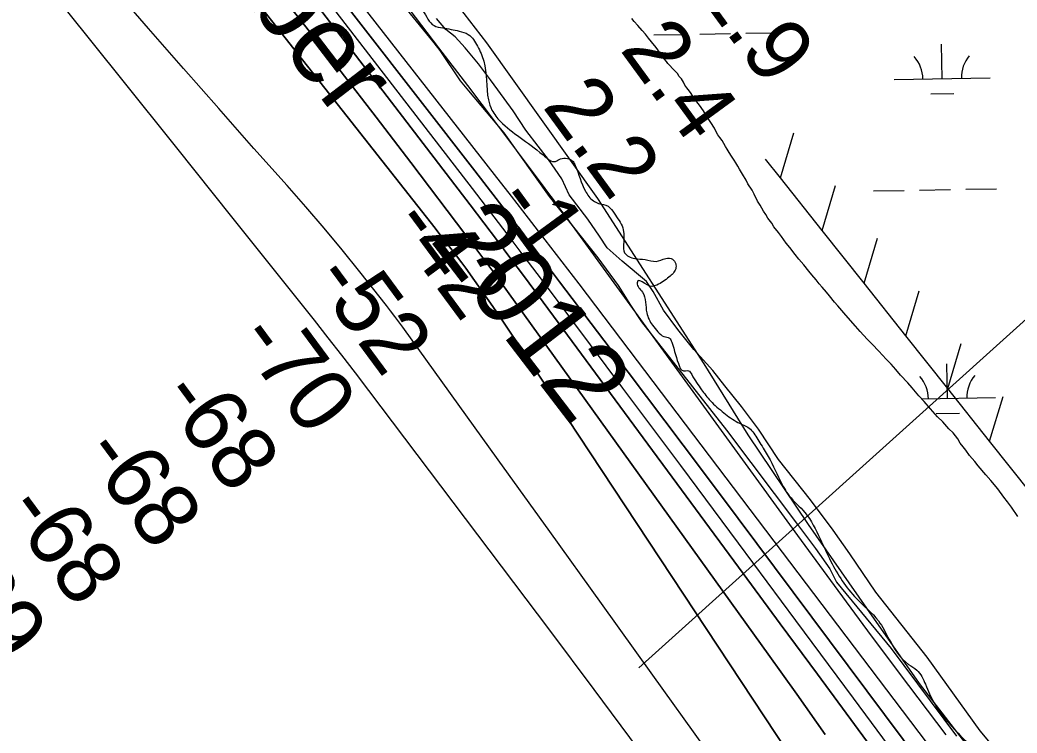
# Model space of a CAD drawing. Extents: x 3887375 to 3925618, y 296674 to 322633.
# Drawn here: x 3903484 to 3904521, y 303211 to 303953 of the extents above; entities that cross this region are included whole.
import ezdxf

# ---------------------------------------------------------------- set-up
doc = ezdxf.new("R2010")
doc.units = 0
for name, color, linetype in [('V-RIVR-EDGE', 7, 'Continuous'), ('V-RIVR-IDEN', 7, 'Continuous'), ('V-RIVR-JETY', 7, 'Continuous'), ('V-RIVR-RANG', 7, 'Continuous'), ('V-RRAP-FSHR', 7, 'Continuous'), ('V-TOPO-DPTH', 7, 'Continuous'), ('V-TOPO-MAJR', 7, 'Continuous'), ('V-TOPO-MINR', 7, 'Continuous'), ('V-TOPO-WATR', 7, 'Continuous'), ('V-WETL-SWMP', 7, 'Continuous')]:
    doc.layers.add(name, color=color, linetype=linetype)

msp = doc.modelspace()

# ---------------------------------------------------------------- linework, layer by layer
at = {"layer": 'V-RIVR-EDGE'}
msp.add_spline([(3903770.8, 304167), (3903771.4, 304174.6), (3903768.5, 304179.6), (3903762.5, 304179.3), (3903755.1, 304174.6), (3903752.1, 304164.7), (3903751.5, 304159), (3903754.8, 304151.4), (3903758.4, 304144.7), (3903757, 304137.4), (3903757, 304131.1), (3903762.3, 304125.4), (3903773.6, 304116.4), (3903785.6, 304106.1), (3903792.2, 304094.1), (3903793.5, 304088.8), (3903799.5, 304081.8), (3903811.4, 304070.8), (3903831.3, 304054.7), (3903842.3, 304049.1), (3903853.6, 304046.7), (3903858.3, 304053), (3903863.9, 304057.3), (3903875.9, 304060.3), (3903902.2, 304051.2), (3903921.7, 304037.9), (3903928.4, 304024.6), (3903933.7, 304014.9), (3903938.6, 304011.6), (3903950.6, 304007.9), (3903951.3, 304004.6), (3903936.6, 303996.3), (3903920, 303988), (3903913.3, 303987.4), (3903903.7, 303986.1), (3903899, 303985.4), (3903896, 303988.4), (3903894.7, 303993.7), (3903890.4, 303996.4), (3903886.4, 303993.4), (3903885, 303990.4), (3903885.4, 303984.8), (3903888, 303978.4), (3903902.9, 303962.1), (3903914.5, 303946.8), (3903923.5, 303944.4), (3903940.8, 303941.1), (3903950.1, 303937.7), (3903959.7, 303925.4), (3903966.3, 303909.8), (3903971.2, 303869.5), (3903974.8, 303858.9), (3903983.5, 303847.2), (3904004, 303830.5), (3904027.9, 303812.2), (3904040.9, 303805.5), (3904046.2, 303808.1), (3904059.2, 303805.4), (3904061.5, 303801.4), (3904072.1, 303774.5), (3904080.3, 303764.5), (3904085.7, 303761.8), (3904095.6, 303758.8), (3904101.9, 303751.5), (3904110.9, 303736.5), (3904111.8, 303719.2), (3904112.8, 303710.5), (3904123.4, 303704.5), (3904134.1, 303703.5), (3904145.7, 303701.5), (3904155.7, 303704.4), (3904162.7, 303703.8), (3904166, 303699.1), (3904166, 303693.8), (3904159, 303685.1), (3904146.3, 303676.9), (3904141, 303675.5), (3904131, 303680.2), (3904126.7, 303681.2), (3904126, 303679.2), (3904131.3, 303669.6), (3904135.9, 303648), (3904141.9, 303635), (3904147.5, 303628.3), (3904153.8, 303623.3), (3904159.5, 303621.6), (3904161.8, 303617.6), (3904170, 303592), (3904172.4, 303588.3), (3904176.3, 303587.7), (3904179.3, 303587.7), (3904182.7, 303583.7), (3904192.9, 303568), (3904202.2, 303556.3), (3904216.1, 303544), (3904230.8, 303534), (3904242.4, 303528), (3904251.3, 303516.3), (3904260.3, 303502), (3904274.8, 303473.4), (3904284.1, 303457.7), (3904300.4, 303440.4), (3904316.2, 303412.7), (3904327.5, 303389.4), (3904354, 303350.8), (3904376.9, 303327.5), (3904388.1, 303308.2), (3904408.4, 303282.2), (3904417, 303276.2), (3904425.9, 303261.5), (3904434.9, 303242.2), (3904460.1, 303210.5), (3904493.5, 303168.2), (3904499.5, 303156.2), (3904515.4, 303136.2), (3904535.3, 303109.9), (3904550.9, 303088.9), (3904578.1, 303056), (3904601.9, 303022), (3904623.1, 302991.7), (3904644, 302960.4), (3904673.8, 302922.4), (3904699.4, 302886.1), (3904723.2, 302853.7), (3904742.4, 302827.4), (3904786.2, 302772.8), (3904807.1, 302745.5), (3904837.2, 302707.5), (3904854.8, 302680.5), (3904867.1, 302662.5), (3904915.8, 302598.2), (3904946.6, 302556.9), (3904978.4, 302512.3), (3905022.2, 302457.3), (3905048.4, 302422.6), (3905069.2, 302392.3), (3905083.5, 302372.7), (3905098, 302354.4)], degree=3, dxfattribs=at)
at = {"layer": 'V-RIVR-JETY'}
for points in [[(3903886.6, 303963), (3903912.8, 303930.6), (3903920.7, 303921), (3903941.7, 303889.5), (3903950.4, 303879), (3903987.1, 303835.3), (3904034.3, 303768.9), (3904085, 303705.1), (3904106, 303676.3), (3904119.1, 303656.1), (3904130.5, 303638.7), (3904218.8, 303525.9), (3904293.9, 303426.3), (3904311.4, 303402.7), (3904326.3, 303381.7), (3904333.3, 303367.7), (3904390.1, 303298.6), (3904458.3, 303207.7)], [(3904520.3, 303168.4), (3904482.7, 303213), (3904427.7, 303289.9), (3904374.4, 303357.2), (3904347.3, 303397.4), (3904329.8, 303421.9), (3904306.2, 303453.4), (3904273, 303495.3), (3904252, 303526.8), (3904234.5, 303550.4), (3904217, 303572.2), (3904204.8, 303588), (3904184.7, 303609.8), (3904168.1, 303630.8), (3904153.2, 303650.9), (3904142.7, 303670.1), (3904135.7, 303680.6), (3904110.4, 303701.6), (3904094.6, 303715.6), (3904086.8, 303727.8), (3904074.5, 303745.3), (3904055.3, 303770.7), (3904047.4, 303787.3), (3904033.5, 303807.4), (3904023, 303821.4), (3904009.9, 303838), (3903996.7, 303858.1), (3903981, 303879.9), (3903973.1, 303890.4), (3903960.9, 303907), (3903946.9, 303923.6), (3903936.4, 303935), (3903926.8, 303942.9), (3903917.2, 303954.2)]]:
    msp.add_lwpolyline(points, dxfattribs=at)
at = {"layer": 'V-RIVR-RANG'}
msp.add_line((3904647.8, 303747), (3904127.6, 303278.7), dxfattribs=at)
at = {"layer": 'V-RRAP-FSHR'}
for p, q in [((3904275, 303788.3), (3904288.8, 303835.1)), ((3904318.5, 303733.5), (3904332.4, 303780.3)), ((3904362.1, 303678.7), (3904376, 303725.5)), ((3904405.6, 303623.9), (3904419.5, 303670.7)), ((3904449.2, 303569.1), (3904463.1, 303615.9)), ((3904492.7, 303514.3), (3904506.6, 303561.1))]:
    msp.add_line(p, q, dxfattribs=at)
for points in [[(3903843.6, 304195.5), (3903802.2, 304154.3), (3903801.2, 304143.7), (3903845.4, 304089.4), (3903969.1, 303928.8), (3904084.5, 303767), (3904195.4, 303595), (3904241.1, 303521.1), (3904304, 303427.8), (3904364.7, 303340.8), (3904419.5, 303262.5), (3904542.9, 303102.6), (3904668, 302949.1), (3904792.2, 302791.8), (3904915.3, 302634.1), (3905037.8, 302475.9), (3905151.7, 302337.7)], [(3904275, 303788.3), (3904259.4, 303807.9)], [(3904318.5, 303733.5), (3904275, 303788.3)], [(3904362.1, 303678.7), (3904318.5, 303733.5)], [(3904405.6, 303623.9), (3904362.1, 303678.7)], [(3904449.2, 303569.1), (3904405.6, 303623.9)], [(3904492.7, 303514.3), (3904449.2, 303569.1)], [(3904536.3, 303459.5), (3904492.7, 303514.3)]]:
    msp.add_lwpolyline(points, dxfattribs=at)
at = {"layer": 'V-TOPO-DPTH'}
for points in [[(3904459.8, 303127.5), (3904230.9, 303434), (3904192.9, 303484.9), (3904154.7, 303535.7), (3904116.5, 303586.4), (3904078.1, 303637), (3904045.2, 303680.4), (3904023.2, 303709.3), (3904001.2, 303738.1), (3903979, 303766.9), (3903956.8, 303795.6), (3903662.9, 304174.5), (3903632.8, 304213.1), (3903602.6, 304251.6), (3903572.2, 304289.9), (3903541.7, 304328.2), (3903527.5, 304345.9), (3903504, 304375.1)], [(3903504, 304375.1), (3903527.5, 304345.9), (3903541.7, 304328.2), (3903572.2, 304289.9), (3903602.6, 304251.6), (3903632.8, 304213.1), (3903662.9, 304174.5), (3903956.8, 303795.6), (3903979, 303766.9), (3904001.2, 303738.1), (3904023.2, 303709.3), (3904045.2, 303680.4), (3904078.1, 303637), (3904116.5, 303586.4), (3904154.7, 303535.7), (3904192.9, 303484.9), (3904230.9, 303434), (3904459.8, 303127.5)], [(3904447.5, 303208.8), (3904408.5, 303260.4), (3904369.7, 303312.1), (3904331.3, 303364.2), (3904293.1, 303416.4), (3904050.2, 303750.3), (3904044.5, 303758), (3904038.8, 303765.8), (3904033.1, 303773.5), (3904027.4, 303781.1), (3903979.4, 303844.9), (3903949.6, 303884.4), (3903919.6, 303923.8), (3903889.5, 303963), (3903859.2, 304002.2), (3903567.5, 304378.2)], [(3904321.7, 303209.4), (3904292, 303251.2), (3904262.2, 303292.8), (3903976.6, 303689.9), (3903969.4, 303699.7), (3903962.3, 303709.5), (3903955, 303719.2), (3903947.7, 303728.9), (3903890.3, 303804.4), (3903854.2, 303851.7), (3903817.8, 303898.8), (3903781.2, 303945.7), (3903744.3, 303992.5), (3903456.7, 304355.3), (3903448.7, 304365.4)], [(3903448.7, 304365.4), (3903456.7, 304355.3), (3903744.3, 303992.5), (3903781.2, 303945.7), (3903817.8, 303898.8), (3903854.2, 303851.7), (3903890.3, 303804.4), (3903947.7, 303728.9), (3903955, 303719.2), (3903962.3, 303709.5), (3903969.4, 303699.7), (3903976.6, 303689.9), (3904262.2, 303292.8), (3904292, 303251.2), (3904321.7, 303209.4)], [(3903475.7, 304370.1), (3903491.3, 304350.7), (3903585.4, 304232.5), (3903647.8, 304153.8), (3903709.9, 304074.8), (3903771.6, 303995.4), (3903832.9, 303915.9), (3903952.1, 303760.2), (3903966.3, 303741.6), (3903980.5, 303722.9), (3903994.5, 303704.1), (3904008.5, 303685.3), (3904236.2, 303376.9), (3904274.8, 303324.5), (3904313.4, 303272.1), (3904352, 303219.7), (3904390.5, 303167.2)], [(3903475.7, 304370.1), (3903491.3, 304350.7), (3903585.4, 304232.5), (3903647.8, 304153.8), (3903709.9, 304074.8), (3903771.6, 303995.4), (3903832.9, 303915.9), (3903952.1, 303760.2), (3903966.3, 303741.6), (3903980.5, 303722.9), (3903994.5, 303704.1), (3904008.5, 303685.3), (3904236.2, 303376.9), (3904274.8, 303324.5), (3904313.4, 303272.1), (3904352, 303219.7), (3904390.5, 303167.2)], [(3904367, 303063.3), (3904004.8, 303611.4), (3903995.2, 303625.8), (3903985.4, 303640.2), (3903975.6, 303654.6), (3903965.6, 303668.8), (3903947.5, 303694.5), (3903944.5, 303698.5), (3903943.5, 303699.9), (3903935.7, 303710.2), (3903930.7, 303716.7), (3903925.7, 303723.1), (3903920.7, 303729.6), (3903915.7, 303736), (3903423.8, 304359.8), (3903422.1, 304362)], [(3903422.1, 304362), (3903423.8, 304359.8), (3903915.7, 303736), (3903920.7, 303729.6), (3903925.7, 303723.1), (3903930.7, 303716.7), (3903935.7, 303710.2), (3903943.5, 303699.9), (3903944.5, 303698.5), (3903947.5, 303694.5), (3903965.6, 303668.8), (3903975.6, 303654.6), (3903985.4, 303640.2), (3903995.2, 303625.8), (3904004.8, 303611.4), (3904367, 303063.3)]]:
    msp.add_lwpolyline(points, dxfattribs=at)
at = {"layer": 'V-TOPO-MAJR'}
msp.add_lwpolyline([(3904195.9, 303196.1), (3904142.3, 303270.9), (3904088.7, 303345.7), (3904035.1, 303420.4), (3903981.3, 303495.1), (3903882.1, 303632.9), (3903877.9, 303638.6), (3903873.6, 303644.3), (3903869.3, 303650), (3903864.9, 303655.6), (3903837.3, 303690.5), (3903818.9, 303713.4), (3903800.2, 303736), (3903781.1, 303758.3), (3903761.7, 303780.4), (3903727.1, 303819.1), (3903690.4, 303860.5), (3903653.8, 303902.1), (3903617.5, 303943.9), (3903581.3, 303985.8), (3903451.4, 304137.7)], dxfattribs=at)
at = {"layer": 'V-TOPO-MINR'}
for points in [[(3904127.3, 303194.1), (3904081.2, 303256), (3904035, 303317.7), (3903846.7, 303567.3), (3903832.7, 303585.6), (3903818.6, 303603.9), (3903804.4, 303622.1), (3903790.1, 303640.2), (3903704.2, 303747.7), (3903646.9, 303819.5), (3903589.5, 303891.2), (3903532.2, 303963), (3903474.8, 304034.7), (3903327.7, 304218.3), (3903308.7, 304242.1), (3903289.8, 304265.9), (3903270.9, 304289.7), (3903252.1, 304313.6), (3903172.5, 304414.6), (3903114.1, 304489.1), (3903056.1, 304563.9), (3902998.5, 304639.1), (3902941.2, 304714.5)], [(3904459.8, 303127.5), (3904230.9, 303434), (3904192.9, 303484.9), (3904154.7, 303535.7), (3904116.5, 303586.4), (3904078.1, 303637), (3904045.2, 303680.4), (3904023.2, 303709.3), (3904001.2, 303738.1), (3903979, 303766.9), (3903956.8, 303795.6), (3903662.9, 304174.5), (3903632.8, 304213.1), (3903602.6, 304251.6), (3903572.2, 304289.9), (3903541.7, 304328.2), (3903527.5, 304345.9), (3903504, 304375.1)], [(3904494.2, 303112.6), (3904117.7, 303609.6), (3904100.3, 303632.5), (3904082.9, 303655.4), (3904065.4, 303678.2), (3904047.9, 303701), (3904030.3, 303723.8), (3904012.7, 303746.6), (3903995, 303769.3), (3903977.3, 303791.9), (3903577.4, 304303.8), (3903563.1, 304321.9), (3903548.8, 304340), (3903534.5, 304358.1), (3903520, 304376.1)], [(3904321.7, 303209.4), (3904292, 303251.2), (3904262.2, 303292.8), (3903976.6, 303689.9), (3903969.4, 303699.7), (3903962.3, 303709.5), (3903955, 303719.2), (3903947.7, 303728.9), (3903890.3, 303804.4), (3903854.2, 303851.7), (3903817.8, 303898.8), (3903781.2, 303945.7), (3903744.3, 303992.5), (3903456.7, 304355.3), (3903448.7, 304365.4)], [(3904390.5, 303167.2), (3904352, 303219.7), (3904313.4, 303272.1), (3904274.8, 303324.5), (3904236.2, 303376.9), (3904008.5, 303685.3), (3903994.5, 303704.1), (3903980.5, 303722.9), (3903966.3, 303741.6), (3903952.1, 303760.2), (3903832.9, 303915.9), (3903771.6, 303995.4), (3903709.9, 304074.8), (3903647.8, 304153.8), (3903585.4, 304232.5), (3903491.3, 304350.7), (3903475.7, 304370.1)], [(3904456.6, 303104.5), (3904351, 303247.1), (3904291.1, 303327.8), (3904231.2, 303408.4), (3904171.2, 303489), (3904111, 303569.5), (3904026.2, 303682.9), (3904008.4, 303706.6), (3903990.5, 303730.2), (3903972.5, 303753.8), (3903954.4, 303777.4), (3903748, 304045.2), (3903702.3, 304104.3), (3903656.3, 304163.2), (3903610, 304221.8), (3903563.5, 304280.3), (3903509.2, 304348.3), (3903489.7, 304372.6)], [(3904367, 303063.3), (3904004.8, 303611.4), (3903995.2, 303625.8), (3903985.4, 303640.2), (3903975.6, 303654.6), (3903965.6, 303668.8), (3903947.5, 303694.5), (3903944.5, 303698.5), (3903943.5, 303699.9), (3903935.7, 303710.2), (3903930.7, 303716.7), (3903925.7, 303723.1), (3903920.7, 303729.6), (3903915.7, 303736), (3903423.8, 304359.8), (3903422.1, 304362)]]:
    msp.add_lwpolyline(points, dxfattribs=at)
at = {"layer": 'V-TOPO-WATR'}
msp.add_lwpolyline([(3904447.5, 303208.8), (3904408.5, 303260.4), (3904369.7, 303312.1), (3904331.3, 303364.2), (3904293.1, 303416.4), (3904050.2, 303750.3), (3904044.5, 303758), (3904038.8, 303765.8), (3904033.1, 303773.5), (3904027.4, 303781.1), (3903979.4, 303844.9), (3903949.6, 303884.4), (3903919.6, 303923.8), (3903889.5, 303963), (3903859.2, 304002.2), (3903567.5, 304378.2)], dxfattribs=at)
at = {"layer": 'V-WETL-SWMP'}
for p, q in [((3904122.6, 303951.2), (3904120.3, 303954.3)), ((3904126.6, 303946.9), (3904122.6, 303951.2)), ((3904131, 303941.7), (3904126.6, 303946.9)), ((3904134.5, 303937.8), (3904131, 303941.7)), ((3904239.1, 303938.8), (3904271.1, 303939.3)), ((3904137.6, 303933.9), (3904134.5, 303937.8)), ((3904140.8, 303930), (3904137.6, 303933.9)), ((3904145.6, 303923.9), (3904140.8, 303930)), ((3904143.1, 303937.1), (3904175.1, 303937.7)), ((3904191.1, 303938), (3904223.1, 303938.5)), ((3904151, 303916.9), (3904145.6, 303923.9)), ((3904443.2, 303891.5), (3904442.6, 303927.5)), ((3904154.1, 303912.1), (3904151, 303916.9)), ((3904156.3, 303909.5), (3904154.1, 303912.1)), ((3904157.7, 303907.4), (3904156.3, 303909.5)), ((3904164.8, 303900), (3904157.7, 303907.4)), ((3904167.9, 303897), (3904164.8, 303900)), ((3904169.6, 303893.9), (3904167.9, 303897)), ((3904171.9, 303891.3), (3904169.6, 303893.9)), ((3904174.1, 303887.8), (3904171.9, 303891.3)), ((3904175.4, 303884.8), (3904174.1, 303887.8)), ((3904393.2, 303890.7), (3904493.2, 303892.4)), ((3904177.7, 303882.2), (3904175.4, 303884.8)), ((3904180.3, 303878.7), (3904177.7, 303882.2)), ((3904182.1, 303876.1), (3904180.3, 303878.7)), ((3904184.3, 303872.6), (3904182.1, 303876.1)), ((3904187.9, 303867.4), (3904184.3, 303872.6)), ((3904190.6, 303863.9), (3904187.9, 303867.4)), ((3904431.5, 303875.9), (3904455.5, 303876.3)), ((3904195, 303858.3), (3904190.6, 303863.9)), ((3904197.2, 303853.9), (3904195, 303858.3)), ((3904200.4, 303849.1), (3904197.2, 303853.9)), ((3904202.6, 303846.1), (3904200.4, 303849.1)), ((3904206.2, 303840), (3904202.6, 303846.1)), ((3904207.9, 303837), (3904206.2, 303840)), ((3904209.7, 303833), (3904207.9, 303837)), ((3904212, 303830.4), (3904209.7, 303833)), ((3904214.2, 303827.4), (3904212, 303830.4)), ((3904217.8, 303820.9), (3904214.2, 303827.4)), ((3904219.5, 303818.2), (3904217.8, 303820.9)), ((3904221.8, 303814.8), (3904219.5, 303818.2)), ((3904224, 303810.9), (3904221.8, 303814.8)), ((3904226.7, 303806.9), (3904224, 303810.9)), ((3904228.5, 303803.9), (3904226.7, 303806.9)), ((3904230.7, 303800.4), (3904228.5, 303803.9)), ((3904232.5, 303797.4), (3904230.7, 303800.4)), ((3904235.6, 303792.1), (3904232.5, 303797.4)), ((3904239.2, 303786.1), (3904235.6, 303792.1)), ((3904241, 303782.1), (3904239.2, 303786.1)), ((3904245.4, 303775.6), (3904241, 303782.1)), ((3904247.7, 303771.3), (3904245.4, 303775.6)), ((3904371.8, 303774.9), (3904403.8, 303775.4)), ((3904419.8, 303775.7), (3904451.8, 303776.2)), ((3904467.8, 303776.5), (3904499.8, 303777.1)), ((3904251.2, 303764.3), (3904247.7, 303771.3)), ((3904253.9, 303759.9), (3904251.2, 303764.3)), ((3904257.5, 303753.8), (3904253.9, 303759.9)), ((3904259.7, 303750.4), (3904257.5, 303753.8)), ((3904262, 303746.4), (3904259.7, 303750.4)), ((3904266, 303741.2), (3904262, 303746.4)), ((3904268.2, 303737.3), (3904266, 303741.2)), ((3904273.1, 303731.7), (3904268.2, 303737.3)), ((3904276.2, 303727.3), (3904273.1, 303731.7)), ((3904281.1, 303720.4), (3904276.2, 303727.3)), ((3904284.6, 303716), (3904281.1, 303720.4)), ((3904290.4, 303708.6), (3904284.6, 303716)), ((3904294, 303703.9), (3904290.4, 303708.6)), ((3904299.3, 303697.8), (3904294, 303703.9)), ((3904304.6, 303691.3), (3904299.3, 303697.8)), ((3904307.7, 303687.4), (3904304.6, 303691.3)), ((3904312.2, 303682.2), (3904307.7, 303687.4)), ((3904315.3, 303678.3), (3904312.2, 303682.2)), ((3904318.4, 303674.8), (3904315.3, 303678.3)), ((3904322.8, 303669.6), (3904318.4, 303674.8)), ((3904325.9, 303665.7), (3904322.8, 303669.6)), ((3904331.3, 303659.2), (3904325.9, 303665.7)), ((3904334.8, 303655.3), (3904331.3, 303659.2)), ((3904341, 303647.9), (3904334.8, 303655.3)), ((3904345.5, 303642.7), (3904341, 303647.9)), ((3904353, 303634), (3904345.5, 303642.7)), ((3904357.9, 303628.4), (3904353, 303634)), ((3904365.4, 303620.6), (3904357.9, 303628.4)), ((3904370.3, 303615.4), (3904365.4, 303620.6)), ((3904377.4, 303608), (3904370.3, 303615.4)), ((3904384.9, 303599.7), (3904377.4, 303608)), ((3904390.3, 303594.5), (3904384.9, 303599.7)), ((3904395.1, 303588.9), (3904390.3, 303594.5)), ((3904400, 303583.3), (3904395.1, 303588.9)), ((3904449, 303558.9), (3904448.3, 303594.9)), ((3904407.6, 303575), (3904400, 303583.3)), ((3904412, 303569.8), (3904407.6, 303575)), ((3904419.1, 303561.6), (3904412, 303569.8)), ((3904424.4, 303555.9), (3904419.1, 303561.6)), ((3904422, 303558.5), (3904498.9, 303559.8)), ((3904431.1, 303548.1), (3904424.4, 303555.9)), ((3904438.6, 303539.9), (3904431.1, 303548.1)), ((3904437.2, 303543.3), (3904461.2, 303543.7)), ((3904443.9, 303534.7), (3904438.6, 303539.9)), ((3904450.1, 303527.3), (3904443.9, 303534.7)), ((3904454.6, 303523), (3904450.1, 303527.3)), ((3904459.5, 303516.9), (3904454.6, 303523)), ((3904462.1, 303512.5), (3904459.5, 303516.9)), ((3904465.2, 303508.6), (3904462.1, 303512.5)), ((3904467.9, 303505.2), (3904465.2, 303508.6)), ((3904471.9, 303499.5), (3904467.9, 303505.2)), ((3904477.2, 303493.4), (3904471.9, 303499.5)), ((3904480.8, 303488.7), (3904477.2, 303493.4)), ((3904488.8, 303479.6), (3904480.8, 303488.7)), ((3904494.1, 303473.5), (3904488.8, 303479.6)), ((3904501.2, 303464.8), (3904494.1, 303473.5)), ((3904507.4, 303456.1), (3904501.2, 303464.8)), ((3904511.4, 303451.3), (3904507.4, 303456.1)), ((3904515.4, 303445.7), (3904511.4, 303451.3)), ((3904522.1, 303436.1), (3904515.4, 303445.7))]:
    msp.add_line(p, q, dxfattribs=at)
for centre, start, end in [((3904388, 303891.1), 0.2115, 41.7552), ((3904498.5, 303893), 140.2115, 181.7552), ((3904393.7, 303558.4), 0.2115, 41.7552), ((3904504.2, 303560.3), 140.2115, 181.7552)]:
    msp.add_arc(centre, 35.2, start, end, dxfattribs=at)

# ---------------------------------------------------------------- texts
at = {"layer": 'V-RIVR-IDEN'}
msp.add_text('September     2012', height=83, rotation=307.4526, dxfattribs=at).set_placement((3903485.2, 304277.5))
at = {"layer": 'V-RIVR-RANG'}
for s, rotation, p in [('2.9', 306.1683, (3904187.5, 303981.5)), ('2.4', 306.1683, (3904107.1, 303922.1)), ('2.2', 306.1683, (3904026.5, 303862.9)), ('-1', 306.1683, (3903975.5, 303763.2)), ('-42', 306.4525, (3903867.8, 303740.5)), ('-52', 306.4525, (3903786, 303682.9)), ('-70', 306.4525, (3903707.4, 303621)), ('-68', 306.4525, (3903627.3, 303561.1)), ('-68', 306.4525, (3903546.7, 303501.9)), ('-68', 306.4525, (3903466.1, 303442.7)), ('-69', 306.4525, (3903386, 303382.8))]:
    msp.add_text(s, height=67, rotation=rotation, dxfattribs=at).set_placement(p)

doc.saveas('drawing.dxf')
